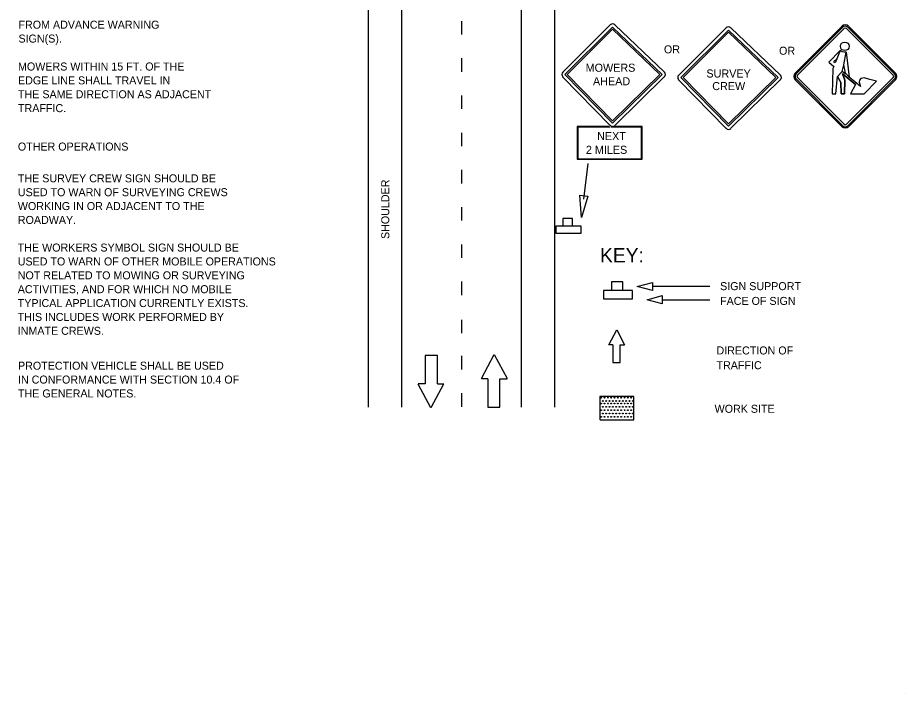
# Model space of a CAD drawing. Extents: x 1531.93 to 1538.58, y 1529.59 to 1539.24.
# Drawn here: x 1531.93 to 1538.58, y 1529.59 to 1534.66 of the extents above; entities that cross this region are included whole.
import ezdxf

# ---------------------------------------------------------------- set-up
doc = ezdxf.new("R2010")
doc.units = 0
for name, color, linetype in [('DETL-DIMS', 7, 'Continuous'), ('DETL-LINE', 7, 'Continuous'), ('DETL-NOTE', 7, 'Continuous'), ('DETL-TITL', 7, 'Continuous'), ('TTLB-TEXT', 7, 'Continuous'), ('USER-BORD', 7, 'Continuous')]:
    doc.layers.add(name, color=color, linetype=linetype)

# ---------------------------------------------------------------- blocks, each defined once
blk = doc.blocks.new('SIGN13')
at = {"layer": 'USER-BORD'}
for points in [[(-0.0134, 0.0182), (0.011, 0.0189), (0.011, 0.0371), (-0.0134, 0.0371)], [(-0.0314, 0.0182), (-0.0314, 0), (0.032, 0), (0.032, 0.0182)]]:
    blk.add_lwpolyline(points, close=True, dxfattribs=at)

msp = doc.modelspace()

# ---------------------------------------------------------------- linework, layer by layer
at = {"layer": 'DETL-DIMS'}
for p, q in [((1536.1744, 1533.2971), (1536.2073, 1533.5627)), ((1536.6856, 1532.6448), (1537.1188, 1532.6448)), ((1536.7584, 1532.5429), (1537.1188, 1532.5429))]:
    msp.add_line(p, q, dxfattribs=at)
for points in [[(1536.1564, 1533.1591), (1536.1443, 1533.3266), (1536.2044, 1533.3201)], [(1536.5746, 1532.6413), (1536.6883, 1532.6715), (1536.6883, 1532.6112)], [(1536.6489, 1532.5429), (1536.7627, 1532.573), (1536.7627, 1532.5127)]]:
    msp.add_lwpolyline(points, close=True, dxfattribs=at)
at = {"layer": 'DETL-LINE'}
for p, q in [((1534.558, 1538.7445), (1534.558, 1531.7359)), ((1534.808, 1538.7445), (1534.808, 1531.7359)), ((1535.7048, 1538.7445), (1535.7048, 1531.7359)), ((1535.9548, 1538.7445), (1535.9548, 1534.3888)), ((1535.2599, 1534.531), (1535.2599, 1534.6319)), ((1538.1101, 1534.592), (1537.7596, 1534.2414)), ((1538.1165, 1534.5862), (1537.7659, 1534.2351)), ((1537.7759, 1534.2251), (1538.127, 1534.5756)), ((1538.1431, 1534.5756), (1538.1434, 1534.5756)), ((1538.494, 1534.2251), (1538.1434, 1534.5756)), ((1538.1434, 1534.5756), (1538.494, 1534.2251)), ((1538.1434, 1534.5756), (1538.494, 1534.2251)), ((1538.5045, 1534.2351), (1538.1539, 1534.5862)), ((1538.5109, 1534.2414), (1538.1603, 1534.592)), ((1535.9548, 1534.3888), (1535.9548, 1531.7359)), ((1538.0125, 1534.3247), (1538.0962, 1534.4102)), ((1538.0125, 1534.3247), (1538.0962, 1534.4102)), ((1538.0962, 1534.4102), (1538.0717, 1534.3493)), ((1538.1113, 1534.4005), (1538.0962, 1534.4102)), ((1538.1261, 1534.3983), (1538.1113, 1534.4005)), ((1538.124, 1534.3034), (1538.1426, 1534.3983)), ((1538.124, 1534.3034), (1538.1426, 1534.3983)), ((1538.1426, 1534.3983), (1538.1261, 1534.3983)), ((1538.1426, 1534.3983), (1538.1628, 1534.2113)), ((1535.2599, 1534.252), (1535.2599, 1534.3529)), ((1538.0125, 1534.3247), (1538.0489, 1534.2921)), ((1538.0717, 1534.3493), (1538.0485, 1534.3273)), ((1538.0485, 1534.3273), (1538.0717, 1534.3493)), ((1538.0717, 1534.3493), (1538.0485, 1534.3273)), ((1538.0571, 1534.3192), (1538.0485, 1534.3273)), ((1538.0717, 1534.3493), (1538.059, 1534.3181)), ((1538.1113, 1534.2538), (1538.124, 1534.3034)), ((1538.1366, 1534.2414), (1538.124, 1534.3034)), ((1538.1354, 1534.2347), (1538.1113, 1534.2538)), ((1538.211, 1534.1555), (1538.1138, 1534.2365)), ((1538.1366, 1534.2414), (1538.1354, 1534.2347)), ((1537.7596, 1534.1912), (1538.1101, 1533.8406)), ((1537.7659, 1534.1976), (1538.1165, 1533.847)), ((1538.127, 1533.8575), (1537.7759, 1534.2081)), ((1538.0635, 1534.0857), (1538.0769, 1534.2149)), ((1538.494, 1534.2081), (1538.1434, 1533.8575)), ((1538.1539, 1533.847), (1538.5045, 1534.1976)), ((1538.1603, 1533.8406), (1538.5109, 1534.1912)), ((1538.2495, 1534.1399), (1538.1628, 1534.2113)), ((1538.2407, 1534.1891), (1538.2384, 1534.1733)), ((1538.2384, 1534.1733), (1538.2495, 1534.1399)), ((1538.2526, 1534.2017), (1538.2407, 1534.1891)), ((1538.2753, 1534.2063), (1538.2526, 1534.2017)), ((1538.318, 1534.1934), (1538.2753, 1534.2063)), ((1538.2753, 1534.086), (1538.3682, 1534.1799)), ((1538.3682, 1534.1799), (1538.318, 1534.1934)), ((1538.211, 1534.1555), (1538.1737, 1534.0857)), ((1535.2599, 1533.973), (1535.2599, 1534.0739)), ((1538.1737, 1534.0857), (1538.2753, 1534.086)), ((1536.1233, 1533.8422), (1536.1233, 1533.5954)), ((1536.3631, 1533.8422), (1536.1233, 1533.8422)), ((1536.1288, 1533.8362), (1536.1288, 1533.5986)), ((1536.3726, 1533.8362), (1536.1288, 1533.8362)), ((1536.6057, 1533.8362), (1536.3799, 1533.8362)), ((1536.6112, 1533.8422), (1536.3894, 1533.8422)), ((1536.6057, 1533.5986), (1536.6057, 1533.8362)), ((1536.6112, 1533.5954), (1536.6112, 1533.8422)), ((1535.2599, 1533.6939), (1535.2599, 1533.7949)), ((1536.1233, 1533.5954), (1536.6112, 1533.5954)), ((1536.1288, 1533.5986), (1536.6057, 1533.5986)), ((1535.2599, 1533.4149), (1535.2599, 1533.5158)), ((1535.2599, 1533.1359), (1535.2599, 1533.2368)), ((1535.2599, 1532.8569), (1535.2599, 1532.9578)), ((1535.2599, 1532.5778), (1535.2599, 1532.6787)), ((1535.2599, 1532.2919), (1535.2599, 1532.3928)), ((1536.3619, 1532.2047), (1536.4208, 1532.3157)), ((1536.4208, 1532.3157), (1536.48, 1532.2047)), ((1536.3907, 1532.204), (1536.361, 1532.204)), ((1536.3907, 1532.204), (1536.3907, 1532.073)), ((1536.4469, 1532.073), (1536.4469, 1532.204)), ((1536.4469, 1532.204), (1536.48, 1532.204)), ((1535.0767, 1532.1235), (1534.9858, 1532.1235)), ((1534.9858, 1532.1235), (1534.9858, 1531.9115)), ((1535.0767, 1531.9115), (1535.0767, 1532.1235)), ((1535.2599, 1532.0198), (1535.2599, 1532.1207)), ((1535.4078, 1531.9513), (1535.5031, 1532.1307)), ((1535.5031, 1532.1307), (1535.599, 1531.9513)), ((1536.3907, 1532.073), (1536.4469, 1532.073)), ((1534.9858, 1531.9115), (1534.9322, 1531.9115)), ((1535.028, 1531.7309), (1534.9322, 1531.9103)), ((1535.1233, 1531.9103), (1535.028, 1531.7309)), ((1535.0767, 1531.9115), (1535.1248, 1531.9115)), ((1535.4545, 1531.9501), (1535.4063, 1531.9501)), ((1535.4545, 1531.9501), (1535.4545, 1531.7381)), ((1535.5453, 1531.7381), (1535.5453, 1531.9501)), ((1535.5453, 1531.9501), (1535.599, 1531.9501)), ((1535.2599, 1531.7408), (1535.2599, 1531.8417)), ((1536.5496, 1531.8173), (1536.2956, 1531.8173)), ((1536.5496, 1531.8173), (1536.2956, 1531.8173)), ((1536.5496, 1531.8173), (1536.2956, 1531.8173)), ((1536.5496, 1531.8173), (1536.2956, 1531.8173)), ((1536.2957, 1531.6433), (1536.2957, 1531.8173)), ((1536.2957, 1531.6434), (1536.2957, 1531.8173)), ((1536.3042, 1531.8084), (1536.3042, 1531.8084)), ((1536.3042, 1531.7646), (1536.3042, 1531.7646)), ((1536.305, 1531.8084), (1536.305, 1531.8084)), ((1536.305, 1531.7646), (1536.305, 1531.7646)), ((1536.317, 1531.7836), (1536.317, 1531.7836)), ((1536.317, 1531.7836), (1536.317, 1531.7836)), ((1536.3298, 1531.8084), (1536.3298, 1531.8084)), ((1536.3298, 1531.8084), (1536.3298, 1531.8084)), ((1536.3298, 1531.7646), (1536.3298, 1531.7646)), ((1536.3298, 1531.7646), (1536.3298, 1531.7646)), ((1536.3418, 1531.7836), (1536.3418, 1531.7836)), ((1536.3418, 1531.7836), (1536.3418, 1531.7836)), ((1536.3546, 1531.8084), (1536.3546, 1531.8084)), ((1536.3546, 1531.7646), (1536.3546, 1531.7646)), ((1536.3554, 1531.8084), (1536.3554, 1531.8084)), ((1536.3554, 1531.7646), (1536.3554, 1531.7646)), ((1536.3674, 1531.7836), (1536.3674, 1531.7836)), ((1536.3674, 1531.7836), (1536.3674, 1531.7836)), ((1536.3794, 1531.8084), (1536.3794, 1531.8084)), ((1536.3794, 1531.7646), (1536.3794, 1531.7646)), ((1536.3802, 1531.8084), (1536.3802, 1531.8084)), ((1536.3802, 1531.7646), (1536.3802, 1531.7646)), ((1536.3922, 1531.7836), (1536.3922, 1531.7836)), ((1536.3922, 1531.7836), (1536.3922, 1531.7836)), ((1536.4042, 1531.8084), (1536.4042, 1531.8084)), ((1536.4042, 1531.7646), (1536.4042, 1531.7646)), ((1536.405, 1531.8084), (1536.405, 1531.8084)), ((1536.405, 1531.7646), (1536.405, 1531.7646)), ((1536.417, 1531.7836), (1536.417, 1531.7836)), ((1536.417, 1531.7836), (1536.417, 1531.7836)), ((1536.4298, 1531.8084), (1536.4298, 1531.8084)), ((1536.4298, 1531.8084), (1536.4298, 1531.8084)), ((1536.4298, 1531.7646), (1536.4298, 1531.7646)), ((1536.4298, 1531.7646), (1536.4298, 1531.7646)), ((1536.4418, 1531.7836), (1536.4418, 1531.7836)), ((1536.4418, 1531.7836), (1536.4418, 1531.7836)), ((1536.4546, 1531.8084), (1536.4546, 1531.8084)), ((1536.4546, 1531.8084), (1536.4546, 1531.8084)), ((1536.4546, 1531.7646), (1536.4546, 1531.7646)), ((1536.4546, 1531.7646), (1536.4546, 1531.7646)), ((1536.4666, 1531.7836), (1536.4666, 1531.7836)), ((1536.4666, 1531.7836), (1536.4666, 1531.7836)), ((1536.4794, 1531.8084), (1536.4794, 1531.8084)), ((1536.4794, 1531.7646), (1536.4794, 1531.7646)), ((1536.4802, 1531.8084), (1536.4802, 1531.8084)), ((1536.4802, 1531.7646), (1536.4802, 1531.7646)), ((1536.4922, 1531.7836), (1536.4922, 1531.7836)), ((1536.4922, 1531.7836), (1536.4922, 1531.7836)), ((1536.5042, 1531.8084), (1536.5042, 1531.8084)), ((1536.5042, 1531.7646), (1536.5042, 1531.7646)), ((1536.505, 1531.8084), (1536.505, 1531.8084)), ((1536.505, 1531.7646), (1536.505, 1531.7646)), ((1536.517, 1531.7836), (1536.517, 1531.7836)), ((1536.517, 1531.7836), (1536.517, 1531.7836)), ((1536.5298, 1531.8084), (1536.5298, 1531.8084)), ((1536.5298, 1531.8084), (1536.5298, 1531.8084)), ((1536.5298, 1531.7646), (1536.5298, 1531.7646)), ((1536.5298, 1531.7646), (1536.5298, 1531.7646)), ((1536.5418, 1531.7836), (1536.5418, 1531.7836)), ((1536.5418, 1531.7836), (1536.5418, 1531.7836)), ((1536.5496, 1531.6433), (1536.5496, 1531.8173)), ((1536.5496, 1531.6433), (1536.5496, 1531.8173)), ((1536.5496, 1531.6433), (1536.5496, 1531.8173)), ((1536.5496, 1531.6433), (1536.5496, 1531.8173)), ((1535.4545, 1531.7381), (1535.5453, 1531.7381)), ((1536.3042, 1531.7142), (1536.3042, 1531.7142)), ((1536.305, 1531.7142), (1536.305, 1531.7142)), ((1536.317, 1531.739), (1536.317, 1531.739)), ((1536.3298, 1531.7142), (1536.3298, 1531.7142)), ((1536.3298, 1531.7142), (1536.3298, 1531.7142)), ((1536.3418, 1531.739), (1536.3418, 1531.739)), ((1536.3546, 1531.7142), (1536.3546, 1531.7142)), ((1536.3554, 1531.7142), (1536.3554, 1531.7142)), ((1536.3674, 1531.739), (1536.3674, 1531.739)), ((1536.3794, 1531.7142), (1536.3794, 1531.7142)), ((1536.3802, 1531.7142), (1536.3802, 1531.7142)), ((1536.3922, 1531.739), (1536.3922, 1531.739)), ((1536.4042, 1531.7142), (1536.4042, 1531.7142)), ((1536.405, 1531.7142), (1536.405, 1531.7142)), ((1536.417, 1531.739), (1536.417, 1531.739)), ((1536.4298, 1531.7142), (1536.4298, 1531.7142)), ((1536.4298, 1531.7142), (1536.4298, 1531.7142)), ((1536.4418, 1531.739), (1536.4418, 1531.739)), ((1536.4546, 1531.7142), (1536.4546, 1531.7142)), ((1536.4546, 1531.7142), (1536.4546, 1531.7142)), ((1536.4666, 1531.739), (1536.4666, 1531.739)), ((1536.4794, 1531.7142), (1536.4794, 1531.7142)), ((1536.4802, 1531.7142), (1536.4802, 1531.7142)), ((1536.4922, 1531.739), (1536.4922, 1531.739)), ((1536.5042, 1531.7142), (1536.5042, 1531.7142)), ((1536.505, 1531.7142), (1536.505, 1531.7142)), ((1536.517, 1531.739), (1536.517, 1531.739)), ((1536.5298, 1531.7142), (1536.5298, 1531.7142)), ((1536.5298, 1531.7142), (1536.5298, 1531.7142)), ((1536.5418, 1531.739), (1536.5418, 1531.739)), ((1536.2957, 1531.6433), (1536.5497, 1531.6433)), ((1536.3042, 1531.665), (1536.3042, 1531.665)), ((1536.305, 1531.665), (1536.305, 1531.665)), ((1536.317, 1531.6894), (1536.317, 1531.6894)), ((1536.317, 1531.6894), (1536.317, 1531.6894)), ((1536.3298, 1531.665), (1536.3298, 1531.665)), ((1536.3298, 1531.665), (1536.3298, 1531.665)), ((1536.3418, 1531.6894), (1536.3418, 1531.6894)), ((1536.3418, 1531.6894), (1536.3418, 1531.6894)), ((1536.3546, 1531.665), (1536.3546, 1531.665)), ((1536.3554, 1531.665), (1536.3554, 1531.665)), ((1536.3674, 1531.6894), (1536.3674, 1531.6894)), ((1536.3674, 1531.6894), (1536.3674, 1531.6894)), ((1536.3794, 1531.665), (1536.3794, 1531.665)), ((1536.3802, 1531.665), (1536.3802, 1531.665)), ((1536.3922, 1531.6894), (1536.3922, 1531.6894)), ((1536.3922, 1531.6894), (1536.3922, 1531.6894)), ((1536.4042, 1531.665), (1536.4042, 1531.665)), ((1536.405, 1531.665), (1536.405, 1531.665)), ((1536.417, 1531.6894), (1536.417, 1531.6894)), ((1536.417, 1531.6894), (1536.417, 1531.6894)), ((1536.4298, 1531.665), (1536.4298, 1531.665)), ((1536.4298, 1531.665), (1536.4298, 1531.665)), ((1536.4418, 1531.6894), (1536.4418, 1531.6894)), ((1536.4418, 1531.6894), (1536.4418, 1531.6894)), ((1536.4546, 1531.665), (1536.4546, 1531.665)), ((1536.4546, 1531.665), (1536.4546, 1531.665)), ((1536.4666, 1531.6894), (1536.4666, 1531.6894)), ((1536.4666, 1531.6894), (1536.4666, 1531.6894)), ((1536.4794, 1531.665), (1536.4794, 1531.665)), ((1536.4802, 1531.665), (1536.4802, 1531.665)), ((1536.4922, 1531.6894), (1536.4922, 1531.6894)), ((1536.4922, 1531.6894), (1536.4922, 1531.6894)), ((1536.5042, 1531.665), (1536.5042, 1531.665)), ((1536.505, 1531.665), (1536.505, 1531.665)), ((1536.517, 1531.6894), (1536.517, 1531.6894)), ((1536.517, 1531.6894), (1536.517, 1531.6894)), ((1536.5298, 1531.665), (1536.5298, 1531.665)), ((1536.5298, 1531.665), (1536.5298, 1531.665)), ((1536.5418, 1531.6894), (1536.5418, 1531.6894)), ((1536.5418, 1531.6894), (1536.5418, 1531.6894))]:
    msp.add_line(p, q, dxfattribs=at)
for points in [[(1536.3722, 1534.6033), (1536.0164, 1534.2493)], [(1536.0332, 1534.2301), (1536.3896, 1534.5859)], [(1536.0506, 1534.2313), (1536.3896, 1534.5703)], [(1536.3896, 1534.5859), (1536.7616, 1534.2319)], [(1536.3896, 1534.5703), (1536.7448, 1534.2313)], [(1536.7802, 1534.2487), (1536.4064, 1534.6039)], [(1537.2415, 1534.5809), (1536.8857, 1534.2269)], [(1536.9025, 1534.2077), (1537.2589, 1534.5635)], [(1537.2589, 1534.5635), (1537.6309, 1534.2095)], [(1537.6495, 1534.2263), (1537.2757, 1534.5815)], [(1536.9199, 1534.2089), (1537.2589, 1534.5479)], [(1537.2589, 1534.5479), (1537.6141, 1534.2089)], [(1538.0489, 1534.2931), (1538.0481, 1534.2906), (1538.0403, 1534.2771), (1538.0353, 1534.0857), (1538.0635, 1534.0857)], [(1536.3902, 1533.8671), (1536.0332, 1534.2301)], [(1536.3902, 1533.8833), (1536.0506, 1534.2313)], [(1536.7616, 1534.2319), (1536.3902, 1533.8671)], [(1536.7448, 1534.2313), (1536.3902, 1533.8833)], [(1538.1628, 1534.2113), (1538.1366, 1534.2414), (1538.136, 1534.238), (1538.1354, 1534.2347), (1538.1113, 1534.2538), (1538.0769, 1534.2149), (1538.1018, 1534.1715), (1538.1045, 1534.085), (1538.1297, 1534.0857), (1538.1302, 1534.1878), (1538.1138, 1534.2365), (1538.211, 1534.1555)], [(1538.113, 1534.236), (1538.1302, 1534.1878), (1538.1297, 1534.0857), (1538.1045, 1534.085), (1538.1018, 1534.1715), (1538.0769, 1534.2149), (1538.0769, 1534.2164)], [(1536.0152, 1534.2145), (1536.3722, 1533.8497)], [(1536.4082, 1533.8503), (1536.779, 1534.2151)], [(1536.8845, 1534.1921), (1537.2415, 1533.8273)], [(1537.2595, 1533.8447), (1536.9025, 1534.2077)], [(1537.2595, 1533.8609), (1536.9199, 1534.2089)], [(1537.6309, 1534.2095), (1537.2595, 1533.8447)], [(1537.6141, 1534.2089), (1537.2595, 1533.8609)], [(1537.2775, 1533.8279), (1537.6483, 1534.1927)]]:
    msp.add_lwpolyline(points, dxfattribs=at)
for centre, radius in [((1538.1303, 1534.4422), 0.0324), ((1536.305, 1531.8084), 0.00291), ((1536.305, 1531.7646), 0.00291), ((1536.317, 1531.7836), 0.00291), ((1536.3298, 1531.8084), 0.00291), ((1536.3298, 1531.7646), 0.00291), ((1536.3418, 1531.7836), 0.00291), ((1536.3554, 1531.8084), 0.00291), ((1536.3554, 1531.7646), 0.00291), ((1536.3674, 1531.7836), 0.00291), ((1536.3802, 1531.8084), 0.00291), ((1536.3802, 1531.7646), 0.00291), ((1536.3922, 1531.7836), 0.00291), ((1536.405, 1531.8084), 0.00291), ((1536.405, 1531.7646), 0.00291), ((1536.417, 1531.7836), 0.00291), ((1536.4298, 1531.8084), 0.00291), ((1536.4298, 1531.7646), 0.00291), ((1536.4418, 1531.7836), 0.00291), ((1536.4546, 1531.8084), 0.00291), ((1536.4546, 1531.7646), 0.00291), ((1536.4666, 1531.7836), 0.00291), ((1536.4802, 1531.8084), 0.00291), ((1536.4802, 1531.7646), 0.00291), ((1536.4922, 1531.7836), 0.00291), ((1536.505, 1531.8084), 0.00291), ((1536.505, 1531.7646), 0.00291), ((1536.517, 1531.7836), 0.00291), ((1536.5298, 1531.8084), 0.00291), ((1536.5298, 1531.7646), 0.00291), ((1536.5418, 1531.7836), 0.00291), ((1536.305, 1531.7142), 0.00291), ((1536.317, 1531.739), 0.00291), ((1536.3298, 1531.7142), 0.00291), ((1536.3418, 1531.739), 0.00291), ((1536.3554, 1531.7142), 0.00291), ((1536.3674, 1531.739), 0.00291), ((1536.3802, 1531.7142), 0.00291), ((1536.3922, 1531.739), 0.00291), ((1536.405, 1531.7142), 0.00291), ((1536.417, 1531.739), 0.00291), ((1536.4298, 1531.7142), 0.00291), ((1536.4418, 1531.739), 0.00291), ((1536.4546, 1531.7142), 0.00291), ((1536.4666, 1531.739), 0.00291), ((1536.4802, 1531.7142), 0.00291), ((1536.4922, 1531.739), 0.00291), ((1536.505, 1531.7142), 0.00291), ((1536.517, 1531.739), 0.00291), ((1536.5298, 1531.7142), 0.00291), ((1536.5418, 1531.739), 0.00291), ((1536.305, 1531.665), 0.00291), ((1536.317, 1531.6894), 0.00291), ((1536.3298, 1531.665), 0.00291), ((1536.3418, 1531.6894), 0.00291), ((1536.3554, 1531.665), 0.00291), ((1536.3674, 1531.6894), 0.00291), ((1536.3802, 1531.665), 0.00291), ((1536.3922, 1531.6894), 0.00291), ((1536.405, 1531.665), 0.00291), ((1536.417, 1531.6894), 0.00291), ((1536.4298, 1531.665), 0.00291), ((1536.4418, 1531.6894), 0.00291), ((1536.4546, 1531.665), 0.00291), ((1536.4666, 1531.6894), 0.00291), ((1536.4802, 1531.665), 0.00291), ((1536.4922, 1531.6894), 0.00291), ((1536.505, 1531.665), 0.00291), ((1536.517, 1531.6894), 0.00291), ((1536.5298, 1531.665), 0.00291), ((1536.5418, 1531.6894), 0.00291)]:
    msp.add_circle(centre, radius, dxfattribs=at)
for centre, radius, start, end in [((1536.3897, 1534.586), 0.0244, 47.72631, 133.5312), ((1537.2589, 1534.5637), 0.0244, 47.72631, 133.5312), ((1538.1348, 1534.5674), 0.0354, 45, 135), ((1538.1348, 1534.5674), 0.0266, 45, 135), ((1538.1348, 1534.5674), 0.0118, 45, 135), ((1536.0338, 1534.2312), 0.0244, 135, 222.51045), ((1536.7623, 1534.2319), 0.0244, 315, 45), ((1536.903, 1534.2089), 0.0244, 135, 222.51045), ((1537.6315, 1534.2095), 0.0244, 315, 45), ((1537.7846, 1534.2165), 0.0354, 135, 225), ((1537.7844, 1534.2166), 0.0266, 135, 225), ((1538.4858, 1534.2166), 0.0266, 315, 45), ((1538.4858, 1534.2166), 0.0354, 315, 45), ((1537.7844, 1534.2166), 0.0118, 135, 225), ((1538.4858, 1534.2166), 0.0118, 315, 45), ((1536.3904, 1533.8667), 0.0244, 220.60129, 315), ((1537.2596, 1533.8443), 0.0244, 220.60129, 315), ((1538.1351, 1533.8659), 0.0354, 225, 315), ((1538.1351, 1533.8659), 0.0266, 225, 315), ((1538.1351, 1533.8659), 0.0118, 225, 315)]:
    msp.add_arc(centre, radius, start, end, dxfattribs=at)
at = {"layer": 'TTLB-TEXT'}
msp.add_line((1538.5844, 1529.5924), (1538.5844, 1529.5924), dxfattribs=at)

# ---------------------------------------------------------------- block references
at = {"layer": 'DETL-LINE'}
for p, xscale, yscale in [((1536.0579, 1533.0407), 2.980410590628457, 2.980410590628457), ((1536.429, 1532.5482), 3.4385190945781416, 3.438519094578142)]:
    msp.add_blockref('SIGN13', p, dxfattribs=dict(at, xscale=xscale, yscale=yscale))

# ---------------------------------------------------------------- texts
for s, p in [('MOWERS', (1536.1879, 1534.2516)), ('AHEAD', (1536.2431, 1534.1501)), ('NEXT', (1536.2739, 1533.7391)), ('2 MILES', (1536.1901, 1533.6362))]:
    msp.add_text(s, height=0.06048, dxfattribs=at).set_placement(p)
at = {"layer": 'DETL-NOTE'}
for s, height, p in [('FROM ADVANCE WARNING', 0.06, (1531.9355, 1534.5744)), ('SIGN(S).', 0.06, (1531.9355, 1534.4704)), ('OR', 0.06, (1536.7751, 1534.3896)), ('OR', 0.06, (1537.6381, 1534.3792)), ('MOWERS WITHIN 15 FT. OF THE', 0.06, (1531.932, 1534.2609)), ('SURVEY', 0.06048, (1537.0935, 1534.2083)), ('EDGE LINE SHALL TRAVEL IN', 0.06, (1531.932, 1534.1569)), ('CREW', 0.06048, (1537.1372, 1534.1141)), ('THE SAME DIRECTION AS ADJACENT', 0.06, (1531.932, 1534.0529)), ('TRAFFIC.', 0.06, (1531.932, 1533.9489)), ('OTHER OPERATIONS', 0.06, (1531.9308, 1533.6607)), ('THE SURVEY CREW SIGN SHOULD BE', 0.06, (1531.9308, 1533.4227)), ('USED TO WARN OF SURVEYING CREWS', 0.06, (1531.9308, 1533.3187)), ('WORKING IN OR ADJACENT TO THE', 0.06, (1531.9308, 1533.2147)), ('ROADWAY.', 0.06, (1531.9308, 1533.1107)), ('THE WORKERS SYMBOL SIGN SHOULD BE', 0.06, (1531.9299, 1532.9035)), ('USED TO WARN OF OTHER MOBILE OPERATIONS', 0.06, (1531.9299, 1532.7995)), ('NOT RELATED TO MOWING OR SURVEYING', 0.06, (1531.9299, 1532.6955)), ('ACTIVITIES, AND FOR WHICH NO MOBILE', 0.06, (1531.9299, 1532.5915)), ('SIGN SUPPORT', 0.06, (1537.1961, 1532.6143)), ('FACE OF SIGN', 0.06, (1537.1961, 1532.5036)), ('TYPICAL APPLICATION CURRENTLY EXISTS.', 0.06, (1531.9299, 1532.4875)), ('THIS INCLUDES WORK PERFORMED BY', 0.06, (1531.9299, 1532.3835)), ('INMATE CREWS.', 0.06, (1531.9299, 1532.2795)), ('DIRECTION OF', 0.06, (1537.1691, 1532.1323)), ('PROTECTION VEHICLE SHALL BE USED', 0.06, (1531.932, 1532.0179)), ('TRAFFIC', 0.06, (1537.1691, 1532.0216)), ('IN CONFORMANCE WITH SECTION 10.4 OF', 0.06, (1531.932, 1531.9139)), ('THE GENERAL NOTES.', 0.06, (1531.932, 1531.8099)), ('WORK SITE', 0.06, (1537.155, 1531.695))]:
    msp.add_text(s, height=height, dxfattribs=at).set_placement(p)
msp.add_text('SHOULDER', height=0.06, rotation=90, dxfattribs=at).set_placement((1534.7157, 1532.9977))
at = {"layer": 'DETL-TITL'}
msp.add_text('KEY:', height=0.108, dxfattribs=at).set_placement((1536.2957, 1532.8221))

doc.saveas('drawing.dxf')
